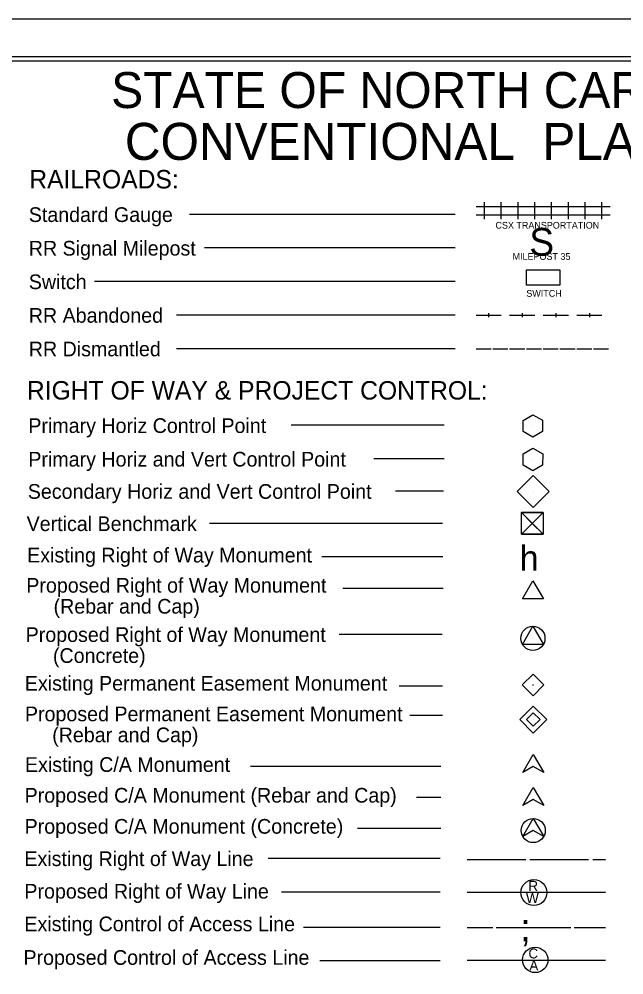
# Model space of a CAD drawing. Extents: x 1523758 to 1525442, y 311788 to 312888.
# Drawn here: x 1524321 to 1524681, y 312319 to 312888 of the extents above; entities that cross this region are included whole.
import ezdxf

# ---------------------------------------------------------------- set-up
doc = ezdxf.new("R2010")
doc.units = 0
for name, color, linetype in [('Default', 7, 'Continuous'), ('Prop ROW Permanent Easement CELL', 7, 'Continuous'), ('Sheet Cutting Line CELL', 7, 'Continuous'), ('Sheet Plot Border Inside CELL', 7, 'Continuous'), ('Sheet Plot Border Outside CELL', 7, 'Continuous'), ('Sheet Symbology CELL', 7, 'Continuous')]:
    doc.layers.add(name, color=color, linetype=linetype)

msp = doc.modelspace()

# ---------------------------------------------------------------- linework, layer by layer
at = {"layer": 'Default'}
for p, q in [((1524626.94, 312646.09), (1524626.94, 312646.09)), ((1524626.93, 312626.12), (1524626.93, 312626.12)), ((1524627.06, 312607.05), (1524627.06, 312607.05)), ((1524626.56, 312588.05), (1524626.56, 312588.05)), ((1524627.03, 312491.83), (1524627.03, 312491.83))]:
    msp.add_line(p, q, dxfattribs=at)
for points in [[(1524626.94, 312639.43), (1524621.14, 312642.73), (1524621.14, 312649.38), (1524626.94, 312652.74), (1524632.73, 312649.45), (1524632.73, 312642.73), (1524626.94, 312639.43)], [(1524633.04, 312594.52), (1524620.07, 312581.55), (1524626.55, 312588.04), (1524633.04, 312581.55), (1524620.07, 312594.52)], [(1524626.55, 312588.04), (1524633.04, 312594.52), (1524620.07, 312594.52), (1524626.55, 312588.04)], [(1524626.55, 312588.04), (1524620.07, 312581.55), (1524633.04, 312581.55), (1524626.55, 312588.04)]]:
    msp.add_lwpolyline(points, dxfattribs=at)
for points in [[(1524621.1, 312629.5), (1524626.96, 312632.77), (1524632.83, 312629.54), (1524632.74, 312622.82), (1524626.87, 312619.42), (1524621.1, 312622.69)], [(1524617.65, 312607.08), (1524627.11, 312616.54), (1524636.59, 312607.06), (1524627.13, 312597.6)], [(1524620.07, 312594.52), (1524633.04, 312594.52), (1524633.04, 312581.55), (1524620.07, 312581.55)], [(1524620.53, 312491.83), (1524627.03, 312498.32), (1524633.52, 312491.83), (1524627.03, 312485.33)]]:
    msp.add_lwpolyline(points, close=True, dxfattribs=at)
msp.add_circle((1524627.03, 312491.83), 0.126, dxfattribs=at)
at = {"layer": 'Prop ROW Permanent Easement CELL'}
msp.add_line((1524627.21, 312471.22), (1524627.21, 312471.22), dxfattribs=at)
for points in [[(1524627.21, 312479.27), (1524635.26, 312471.22), (1524627.21, 312463.17), (1524619.15, 312471.22)], [(1524627.21, 312475.24), (1524631.23, 312471.22), (1524627.21, 312467.19), (1524623.18, 312471.22)]]:
    msp.add_lwpolyline(points, close=True, dxfattribs=at)
at = {"layer": 'Sheet Cutting Line CELL'}
msp.add_line((1525442.07, 312888.39), (1523758.07, 312888.39), dxfattribs=at)
msp.add_line((1525442.07, 312888.39), (1523758.07, 312888.39), dxfattribs=at)
at = {"layer": 'Sheet Plot Border Inside CELL'}
msp.add_lwpolyline([(1523771.07, 311810.84), (1525437.57, 311810.84), (1525437.57, 312865.94), (1523771.07, 312865.94)], close=True, dxfattribs=at)
at = {"layer": 'Sheet Plot Border Outside CELL'}
msp.add_lwpolyline([(1523758.07, 311788.39), (1525442.07, 311788.39), (1525442.07, 312888.39), (1523758.07, 312888.39)], close=True, dxfattribs=at)
at = {"layer": 'Sheet Symbology CELL'}
for p, q in [((1524593.09, 312776.84), (1524603.09, 312776.84)), ((1524598.09, 312769.34), (1524598.09, 312779.34)), ((1524603.09, 312776.84), (1524613.09, 312776.84)), ((1524608.09, 312769.34), (1524608.09, 312779.34)), ((1524613.09, 312776.84), (1524623.09, 312776.84)), ((1524618.09, 312769.34), (1524618.09, 312779.34)), ((1524623.09, 312776.84), (1524633.09, 312776.84)), ((1524628.09, 312769.34), (1524628.09, 312779.34)), ((1524633.09, 312776.84), (1524643.09, 312776.84)), ((1524638.09, 312769.34), (1524638.09, 312779.34)), ((1524643.09, 312776.84), (1524653.09, 312776.84)), ((1524648.09, 312769.34), (1524648.09, 312779.34)), ((1524653.09, 312776.84), (1524663.09, 312776.84)), ((1524658.09, 312769.34), (1524658.09, 312779.34)), ((1524663.09, 312776.84), (1524673.09, 312776.84)), ((1524668.09, 312769.34), (1524668.09, 312779.34)), ((1524580.7, 312772.08), (1524422.28, 312772.08)), ((1524593.09, 312771.84), (1524603.09, 312771.84)), ((1524603.09, 312771.84), (1524613.09, 312771.84)), ((1524613.09, 312771.84), (1524623.09, 312771.84)), ((1524623.09, 312771.84), (1524633.09, 312771.84)), ((1524633.09, 312771.84), (1524643.09, 312771.84)), ((1524643.09, 312771.84), (1524653.09, 312771.84)), ((1524653.09, 312771.84), (1524663.09, 312771.84)), ((1524663.09, 312771.84), (1524673.09, 312771.84)), ((1524580.7, 312752.08), (1524431.15, 312752.08)), ((1524580.7, 312732.08), (1524365.78, 312732.08)), ((1524580.7, 312712.08), (1524414.53, 312712.08)), ((1524593.09, 312712.08), (1524608.09, 312712.08)), ((1524600.59, 312713.33), (1524600.59, 312710.83)), ((1524613.09, 312712.08), (1524628.09, 312712.08)), ((1524620.59, 312713.33), (1524620.59, 312710.83)), ((1524633.09, 312712.08), (1524648.09, 312712.08)), ((1524640.59, 312713.33), (1524640.59, 312710.83)), ((1524653.09, 312712.08), (1524668.09, 312712.08)), ((1524660.59, 312713.33), (1524660.59, 312710.83)), ((1524580.7, 312692.08), (1524414.53, 312692.08)), ((1524580.7, 312692.08), (1524414.53, 312692.08)), ((1524593.09, 312692.08), (1524602.09, 312692.08)), ((1524603.09, 312692.08), (1524612.09, 312692.08)), ((1524613.09, 312692.08), (1524622.09, 312692.08)), ((1524623.09, 312692.08), (1524632.09, 312692.08)), ((1524633.09, 312692.08), (1524642.09, 312692.08)), ((1524643.09, 312692.08), (1524652.09, 312692.08)), ((1524653.09, 312692.08), (1524662.09, 312692.08)), ((1524663.09, 312692.08), (1524672.09, 312692.08)), ((1524574.01, 312646.46), (1524482.97, 312646.46)), ((1524574.01, 312626.46), (1524532.09, 312626.46)), ((1524573.69, 312607.25), (1524545.14, 312607.25)), ((1524573, 312588.03), (1524434.16, 312588.03)), ((1524573.32, 312568.05), (1524501.26, 312568.05)), ((1524573.41, 312549.27), (1524513.68, 312549.27)), ((1524626.93, 312546.65), (1524626.93, 312546.65)), ((1524572.91, 312521.86), (1524511.43, 312521.86)), ((1524626.95, 312519.59), (1524626.95, 312519.59)), ((1524572.99, 312491.17), (1524547.2, 312491.17)), ((1524572.99, 312473.55), (1524553.71, 312473.55)), ((1524620.94, 312439.64), (1524627.19, 312450.44)), ((1524627.19, 312450.44), (1524633.44, 312439.64)), ((1524572, 312443.33), (1524458.76, 312443.33)), ((1524627.19, 312443.24), (1524620.94, 312439.64)), ((1524633.44, 312439.64), (1524627.19, 312443.24)), ((1524620.9, 312420.03), (1524627.15, 312430.83)), ((1524627.15, 312430.83), (1524633.4, 312420.03)), ((1524572.1, 312424.8), (1524557.53, 312424.8)), ((1524627.15, 312423.63), (1524620.9, 312420.03)), ((1524633.4, 312420.03), (1524627.15, 312423.63)), ((1524620.9, 312401.52), (1524627.15, 312412.32)), ((1524627.15, 312412.32), (1524633.4, 312401.52)), ((1524572.1, 312406.29), (1524522.43, 312406.29)), ((1524627.15, 312405.12), (1524620.9, 312401.52)), ((1524633.4, 312401.52), (1524627.15, 312405.12)), ((1524571.66, 312388.51), (1524469.14, 312388.51)), ((1524587.69, 312387.94), (1524622.69, 312387.94)), ((1524625.19, 312387.94), (1524660.19, 312387.94)), ((1524662.69, 312387.94), (1524670.19, 312387.94)), ((1524571.66, 312368.51), (1524477.13, 312368.51)), ((1524587.69, 312368.39), (1524670.19, 312368.39)), ((1524571.66, 312347.39), (1524490.34, 312347.39)), ((1524587.69, 312347.39), (1524603.15, 312347.39)), ((1524605.15, 312347.39), (1524649.56, 312347.39)), ((1524651.56, 312347.39), (1524670.19, 312347.39)), ((1524571.66, 312327.57), (1524500.01, 312327.57)), ((1524587.69, 312327.95), (1524670.19, 312327.95))]:
    msp.add_line(p, q, dxfattribs=at)
for points in [[(1525425.07, 312863.39), (1523925.07, 312863.39), (1523925.07, 311814.41), (1525425.07, 311814.41)], [(1524623.09, 312739.04), (1524643.09, 312739.04), (1524643.09, 312729.94), (1524623.09, 312729.94)], [(1524620.68, 312543.05), (1524626.93, 312553.85), (1524633.18, 312543.05)], [(1524620.7, 312515.99), (1524626.95, 312526.79), (1524633.2, 312515.99)]]:
    msp.add_lwpolyline(points, close=True, dxfattribs=at)
for centre, radius in [((1524626.95, 312519.59), 7.2), ((1524627.15, 312405.12), 7.2), ((1524627.54, 312368.18), 7.75), ((1524628.34, 312328.06), 7.58)]:
    msp.add_circle(centre, radius, dxfattribs=at)

# ---------------------------------------------------------------- texts
for s, height, p in [('STATE OF NORTH CAROLINA, DIVISION OF HIGHWAYS', 21.419, (1524375.63, 312835.43)), ('CONVENTIONAL  PLAN SHEET SYMBOLS', 22.0323, (1524383.76, 312804.55)), ('RAILROADS:', 11, (1524326.81, 312787.53)), ('Standard Gauge', 8.75, (1524326.53, 312767.56)), ('S', 16.5, (1524624.85, 312747.46)), ('RR Signal Milepost', 8.75, (1524326.53, 312747.56)), ('Switch', 8.75, (1524326.53, 312727.56)), ('RR Abandoned', 8.75, (1524326.53, 312707.56)), ('RR Dismantled', 8.75, (1524326.53, 312687.56)), ('RIGHT OF WAY & PROJECT CONTROL:', 11, (1524325.4, 312661.8)), ('Primary Horiz Control Point', 8.75, (1524326.26, 312641.91)), ('Primary Horiz and Vert Control Point', 8.75, (1524326.26, 312621.91)), ('Secondary Horiz and Vert Control Point', 8.75, (1524325.94, 312602.7)), ('Vertical Benchmark', 8.75, (1524325.25, 312583.48)), ('h', 15, (1524619.16, 312559.87)), ('Existing Right of Way Monument', 8.75, (1524325.57, 312564.77)), ('Proposed Right of Way Monument', 8.75, (1524325.05, 312546.8)), ('     (Rebar and Cap)', 8.75, (1524325.05, 312534.3)), ('Proposed Right of Way Monument', 8.75, (1524324.67, 312517.45)), ('     (Concrete)', 8.75, (1524324.67, 312504.95)), ('Existing Permanent Easement Monument', 8.75, (1524324.19, 312488.46)), ('Proposed Permanent Easement Monument', 8.75, (1524324.23, 312470.22)), ('     (Rebar and Cap)', 8.75, (1524324.23, 312457.72)), ('Existing C/A Monument', 8.75, (1524324.25, 312440.05)), ('Proposed C/A Monument (Rebar and Cap)', 8.75, (1524324.04, 312421.74)), ('Proposed C/A Monument (Concrete)', 8.75, (1524324.04, 312403.24)), ('Existing Right of Way Line', 8.75, (1524323.91, 312383.96)), ('Proposed Right of Way Line', 8.75, (1524323.91, 312364.59)), ('R', 6.08, (1524624.21, 312369.09)), ('W', 6.08, (1524622.82, 312361.94)), ('Existing Control of Access Line', 8.75, (1524323.91, 312345.13)), (';', 16.5, (1524619.48, 312339.2)), ('Proposed Control of Access Line', 8.75, (1524323.36, 312325.14)), ('C', 5.94, (1524624.31, 312328.95)), ('A', 5.94, (1524624.9, 312321.81))]:
    msp.add_text(s, height=height, dxfattribs=at).set_placement(p)
for s, p in [('CSX TRANSPORTATION', (1524604.65, 312763.61)), ('MILEPOST 35', (1524614.84, 312745.03)), ('SWITCH', (1524623.04, 312723.03))]:
    msp.add_text(s, height=4, rotation=360, dxfattribs=at).set_placement(p)

doc.saveas('drawing.dxf')
